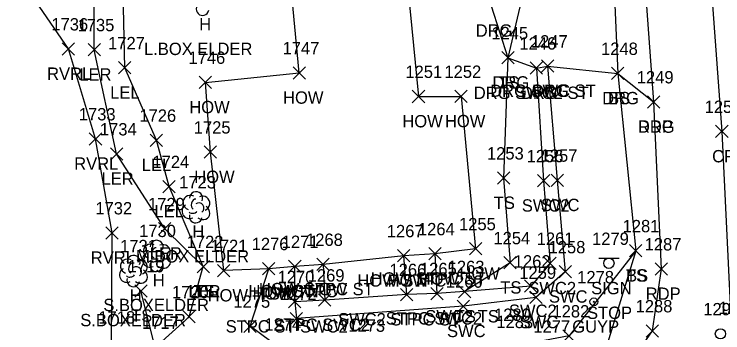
# Model space of a CAD drawing. Extents: x 1461855 to 1464118, y 556196 to 557441.
# Drawn here: x 1462302.6 to 1462417.3, y 556452.7 to 556504.3 of the extents above; entities that cross this region are included whole.
import ezdxf

# ---------------------------------------------------------------- set-up
doc = ezdxf.new("R2010")
doc.units = 0
for name, color, linetype in [('L_A', 7, 'Continuous'), ('L_C', 7, 'Continuous'), ('L_I', 7, 'Continuous'), ('L_TIC', 7, 'Continuous'), ('LARO', 7, 'Continuous'), ('LAWE', 7, 'Continuous'), ('LBC', 7, 'Continuous'), ('LBF', 7, 'Continuous'), ('LELB', 7, 'Continuous'), ('LTD', 7, 'Continuous'), ('P_A', 7, 'Continuous'), ('P_I', 7, 'Continuous'), ('P_TIC', 7, 'Continuous'), ('PET', 7, 'Continuous'), ('PRC', 7, 'Continuous'), ('R_A', 7, 'Continuous'), ('R_I', 7, 'Continuous'), ('R_TIC', 7, 'Continuous'), ('RDG', 7, 'Continuous'), ('RSW', 7, 'Continuous'), ('S_A', 7, 'Continuous'), ('S_C', 7, 'Continuous'), ('S_I', 7, 'Continuous'), ('SSGN', 7, 'Continuous'), ('U_A', 7, 'Continuous'), ('U_I', 7, 'Continuous'), ('UPGW', 7, 'Continuous'), ('UUMH', 7, 'Continuous')]:
    doc.layers.add(name, color=color, linetype=linetype)

msp = doc.modelspace()

# ---------------------------------------------------------------- linework, layer by layer
at = {"layer": 'L_TIC'}
for points in [[(1462310.37, 556497.7), (1462312.37, 556499.7)], [(1462312.37, 556497.7), (1462310.37, 556499.7)], [(1462314.55, 556497.58), (1462316.55, 556499.58)], [(1462316.55, 556497.58), (1462314.55, 556499.58)], [(1462381.5, 556496.28), (1462383.5, 556498.28)], [(1462383.5, 556496.28), (1462381.5, 556498.28)], [(1462319.5, 556494.65), (1462321.5, 556496.65)], [(1462321.5, 556494.65), (1462319.5, 556496.65)], [(1462347.73, 556493.83), (1462349.73, 556495.83)], [(1462349.73, 556493.83), (1462347.73, 556495.83)], [(1462399.26, 556493.74), (1462401.26, 556495.74)], [(1462401.26, 556493.74), (1462399.26, 556495.74)], [(1462332.55, 556492.29), (1462334.55, 556494.29)], [(1462334.55, 556492.29), (1462332.55, 556494.29)], [(1462367.02, 556490), (1462369.02, 556492)], [(1462369.02, 556490), (1462367.02, 556492)], [(1462373.91, 556490.02), (1462375.91, 556492.02)], [(1462375.91, 556490.02), (1462373.91, 556492.02)], [(1462314.76, 556483.13), (1462316.76, 556485.13)], [(1462316.76, 556483.13), (1462314.76, 556485.13)], [(1462324.61, 556482.91), (1462326.61, 556484.91)], [(1462326.61, 556482.91), (1462324.61, 556484.91)], [(1462318.16, 556480.69), (1462320.16, 556482.69)], [(1462320.16, 556480.69), (1462318.16, 556482.69)], [(1462333.35, 556480.99), (1462335.35, 556482.99)], [(1462335.35, 556480.99), (1462333.35, 556482.99)], [(1462380.8, 556476.79), (1462382.8, 556478.79)], [(1462382.8, 556476.79), (1462380.8, 556478.79)], [(1462326.67, 556475.4), (1462328.67, 556477.4)], [(1462328.67, 556475.4), (1462326.67, 556477.4)], [(1462317.43, 556467.89), (1462319.43, 556469.89)], [(1462319.43, 556467.89), (1462317.43, 556469.89)], [(1462325.96, 556468.57), (1462327.96, 556470.57)], [(1462327.96, 556468.57), (1462325.96, 556470.57)], [(1462369.67, 556464.51), (1462371.67, 556466.51)], [(1462371.67, 556464.51), (1462369.67, 556466.51)], [(1462369.67, 556464.51), (1462371.67, 556466.51)], [(1462371.67, 556464.51), (1462369.67, 556466.51)], [(1462376.27, 556465.33), (1462378.27, 556467.33)], [(1462378.27, 556465.33), (1462376.27, 556467.33)], [(1462402.17, 556465), (1462404.17, 556467)], [(1462404.17, 556465), (1462402.17, 556467)], [(1462402.17, 556465), (1462404.17, 556467)], [(1462404.17, 556465), (1462402.17, 556467)], [(1462364.63, 556464.19), (1462366.63, 556466.19)], [(1462366.63, 556464.19), (1462364.63, 556466.19)], [(1462364.63, 556464.19), (1462366.63, 556466.19)], [(1462366.63, 556464.19), (1462364.63, 556466.19)], [(1462332.2, 556462.44), (1462334.2, 556464.44)], [(1462334.2, 556462.44), (1462332.2, 556464.44)], [(1462332.2, 556462.44), (1462334.2, 556464.44)], [(1462334.2, 556462.44), (1462332.2, 556464.44)], [(1462332.2, 556462.44), (1462334.2, 556464.44)], [(1462334.2, 556462.44), (1462332.2, 556464.44)], [(1462342.78, 556462.1), (1462344.78, 556464.1)], [(1462344.78, 556462.1), (1462342.78, 556464.1)], [(1462342.78, 556462.1), (1462344.78, 556464.1)], [(1462344.78, 556462.1), (1462342.78, 556464.1)], [(1462347.01, 556462.46), (1462349.01, 556464.46)], [(1462349.01, 556462.46), (1462347.01, 556464.46)], [(1462347.01, 556462.46), (1462349.01, 556464.46)], [(1462349.01, 556462.46), (1462347.01, 556464.46)], [(1462351.57, 556462.79), (1462353.57, 556464.79)], [(1462353.57, 556462.79), (1462351.57, 556464.79)], [(1462351.57, 556462.79), (1462353.57, 556464.79)], [(1462353.57, 556462.79), (1462351.57, 556464.79)], [(1462381.84, 556463.06), (1462383.84, 556465.06)], [(1462383.84, 556463.06), (1462381.84, 556465.06)], [(1462335.52, 556461.79), (1462337.52, 556463.79)], [(1462337.52, 556461.79), (1462335.52, 556463.79)], [(1462322.11, 556458.5), (1462324.11, 556460.5)], [(1462324.11, 556458.5), (1462322.11, 556460.5)], [(1462365.12, 556457.9), (1462367.12, 556459.9)], [(1462367.12, 556457.9), (1462365.12, 556459.9)], [(1462370, 556458.05), (1462372, 556460.05)], [(1462372, 556458.05), (1462370, 556460.05)], [(1462374.48, 556458.39), (1462376.48, 556460.39)], [(1462376.48, 556458.39), (1462374.48, 556460.39)], [(1462347, 556456.75), (1462349, 556458.75)], [(1462349, 556456.75), (1462347, 556458.75)], [(1462351.85, 556457.01), (1462353.85, 556459.01)], [(1462353.85, 556457.01), (1462351.85, 556459.01)], [(1462329.91, 556454.31), (1462331.91, 556456.31)], [(1462331.91, 556454.31), (1462329.91, 556456.31)], [(1462339.76, 556452.77), (1462341.76, 556454.77)], [(1462341.76, 556452.77), (1462339.76, 556454.77)], [(1462391.39, 556451.19), (1462393.39, 556453.19)], [(1462393.39, 556451.19), (1462391.39, 556453.19)]]:
    msp.add_lwpolyline(points, dxfattribs=at)
at = {"layer": 'LARO'}
for points in [[(1462333.2, 556463.44), (1462326.96, 556469.57), (1462319.16, 556481.69), (1462315.55, 556498.58), (1462315.61, 556513.99), (1462326.32, 556521.07)], [(1462333.2, 556463.44), (1462327.67, 556476.4), (1462325.61, 556483.91), (1462320.5, 556495.65), (1462320.11, 556512.8), (1462326.32, 556521.07)]]:
    msp.add_lwpolyline(points, dxfattribs=at)
at = {"layer": 'LAWE'}
msp.add_lwpolyline([(1462349.42, 556312.26), (1462347.88, 556323.02), (1462343.78, 556341.46), (1462337.18, 556366.3), (1462336.39, 556385.54), (1462332.39, 556400.16), (1462328.25, 556406.01), (1462322.28, 556416.09), (1462319.22, 556425.25), (1462318.05, 556436.55), (1462318.36, 556451.21), (1462318.43, 556468.89), (1462315.76, 556484.13), (1462311.37, 556498.7), (1462302.6, 556511.6)], dxfattribs=at)
at = {"layer": 'LBC'}
msp.add_lwpolyline([(1462365.55, 556516.39), (1462368.02, 556491), (1462374.91, 556491.02), (1462377.27, 556466.33), (1462370.67, 556465.51), (1462365.63, 556465.19), (1462352.57, 556463.79), (1462348.01, 556463.46), (1462343.78, 556463.1), (1462336.52, 556462.79), (1462334.35, 556481.99), (1462333.55, 556493.29), (1462348.73, 556494.83), (1462346.86, 556514.38), (1462349.85, 556514.8), (1462349.13, 556520.74), (1462355.11, 556521.53), (1462355.47, 556515.9)], dxfattribs=at)
at = {"layer": 'LBF'}
for points in [[(1462370.67, 556465.51), (1462371, 556459.05)], [(1462366.12, 556458.9), (1462365.63, 556465.19)], [(1462348, 556457.75), (1462348.01, 556463.46)], [(1462352.57, 556463.79), (1462352.85, 556458.01)]]:
    msp.add_lwpolyline(points, dxfattribs=at)
at = {"layer": 'LELB'}
for points in [[(1462392.6, 556582.28), (1462394.16, 556573.28), (1462392.25, 556560.75), (1462384.18, 556539.63), (1462388.23, 556521.88), (1462382.5, 556497.28), (1462381.8, 556477.79), (1462382.84, 556464.06), (1462375.48, 556459.39)], [(1462397.76, 556560.35), (1462398.93, 556525.64), (1462400.26, 556494.74), (1462403.17, 556466), (1462397.35, 556446.97), (1462388.69, 556445.8), (1462367.43, 556444.36), (1462357.72, 556443.74), (1462341.15, 556446.51)], [(1462403.17, 556466), (1462392.39, 556452.19), (1462383.31, 556450.47), (1462367.43, 556444.36)], [(1462328.51, 556438.01), (1462325.41, 556450.35), (1462330.91, 556455.31), (1462333.2, 556463.44)], [(1462359.35, 556449.87), (1462345.78, 556450.06), (1462340.76, 556453.77), (1462343.78, 556463.1)], [(1462327.98, 556421.29), (1462322.63, 556425.06), (1462324.05, 556436.25), (1462325.41, 556450.35), (1462323.11, 556459.5)]]:
    msp.add_lwpolyline(points, dxfattribs=at)
at = {"layer": 'LTD'}
for p, q in [((1462331.99, 556473.1), (1462331.99, 556473.1)), ((1462331.99, 556473.1), (1462331.99, 556473.1)), ((1462325.6, 556465.22), (1462325.6, 556465.22)), ((1462325.6, 556465.22), (1462325.6, 556465.22)), ((1462321.88, 556462.77), (1462321.88, 556462.77)), ((1462321.88, 556462.77), (1462321.88, 556462.77))]:
    msp.add_line(p, q, dxfattribs=at)
for centre in [(1462332.04, 556474.53), (1462325.65, 556466.65), (1462321.92, 556464.2)]:
    msp.add_arc(centre, 1.05, 335.5272, 180.9563, dxfattribs=at)
for centre, major_axis, ratio, start_param, end_param in [((1462333.09, 556505.22), (0.26, 1.06), 0.942809, 1.570796, 4.712389), ((1462331.2, 556473.77), (1.21, -0.51), 0.895232, 1.570796, 4.712389), ((1462331.78, 556473.56), (-0.208, -0.792), 0.645439, 3.141593, 6.283185), ((1462333.03, 556473.68), (-1.14, -0.48), 0.949671, 1.570796, 4.712389), ((1462330.91, 556472.39), (0.58, -1.04), 0.959034, 3.141593, 6.283185), ((1462332.49, 556472.93), (-0.5, 0.667), 0.989748, 3.141593, 6.283185), ((1462331.53, 556472.35), (-0.625, -0.083), 0.423636, 0, 3.141593), ((1462332.99, 556472.27), (-1.09, 0.79), 0.841452, 1.570796, 4.712389), ((1462331.99, 556471.6), (0.26, 1.06), 0.942809, 1.570796, 4.712389), ((1462324.81, 556465.88), (1.21, -0.51), 0.895232, 1.570796, 4.712389), ((1462325.39, 556465.68), (-0.208, -0.792), 0.645439, 3.141593, 6.283185), ((1462326.64, 556465.8), (-1.14, -0.48), 0.949671, 1.570796, 4.712389), ((1462324.52, 556464.51), (0.58, -1.04), 0.959034, 3.141593, 6.283185), ((1462326.1, 556465.05), (-0.5, 0.667), 0.989748, 3.141593, 6.283185), ((1462326.6, 556464.38), (-1.09, 0.79), 0.841452, 1.570796, 4.712389), ((1462321.08, 556463.44), (1.21, -0.51), 0.895232, 1.570796, 4.712389), ((1462321.67, 556463.23), (-0.208, -0.792), 0.645439, 3.141593, 6.283185), ((1462322.92, 556463.35), (-1.14, -0.48), 0.949671, 1.570796, 4.712389), ((1462325.14, 556464.47), (-0.625, -0.083), 0.423636, 0, 3.141593), ((1462320.79, 556462.06), (0.58, -1.04), 0.959034, 3.141593, 6.283185), ((1462322.38, 556462.6), (-0.5, 0.667), 0.989748, 3.141593, 6.283185), ((1462325.6, 556463.72), (0.26, 1.06), 0.942809, 1.570796, 4.712389), ((1462321.42, 556462.02), (-0.625, -0.083), 0.423636, 0, 3.141593), ((1462322.88, 556461.94), (-1.09, 0.79), 0.841452, 1.570796, 4.712389), ((1462321.88, 556461.27), (0.26, 1.06), 0.942809, 1.570796, 4.712389)]:
    msp.add_ellipse(centre, major_axis=major_axis, ratio=ratio, start_param=start_param, end_param=end_param, dxfattribs=at)
at = {"layer": 'P_TIC'}
for points in [[(1462405.05, 556489.12), (1462407.05, 556491.12)], [(1462407.05, 556489.12), (1462405.05, 556491.12)], [(1462416.1, 556484.33), (1462418.1, 556486.33)], [(1462418.1, 556484.33), (1462416.1, 556486.33)], [(1462406.3, 556462.05), (1462408.3, 556464.05)], [(1462408.3, 556462.05), (1462406.3, 556464.05)], [(1462404.84, 556452.02), (1462406.84, 556454.02)], [(1462406.84, 556452.02), (1462404.84, 556454.02)]]:
    msp.add_lwpolyline(points, dxfattribs=at)
at = {"layer": 'PET'}
msp.add_lwpolyline([(1462398.06, 556593.15), (1462400.02, 556575.06), (1462401.08, 556560.86), (1462403.29, 556527.85), (1462406.05, 556490.12), (1462407.3, 556463.05), (1462405.84, 556453.02), (1462399.79, 556444.3), (1462382.48, 556434.45)], dxfattribs=at)
at = {"layer": 'PRC'}
msp.add_lwpolyline([(1462408.92, 556592.16), (1462412.2, 556557.56), (1462413.99, 556527.84), (1462417.1, 556485.33), (1462418.69, 556452.73), (1462415.65, 556430.87), (1462414.08, 556417.65)], dxfattribs=at)
at = {"layer": 'R_TIC'}
for points in [[(1462381.5, 556496.28), (1462383.5, 556498.28)], [(1462383.5, 556496.28), (1462381.5, 556498.28)], [(1462386.1, 556494.6), (1462388.1, 556496.6)], [(1462388.1, 556494.6), (1462386.1, 556496.6)], [(1462386.1, 556494.6), (1462388.1, 556496.6)], [(1462388.1, 556494.6), (1462386.1, 556496.6)], [(1462387.91, 556494.94), (1462389.91, 556496.94)], [(1462389.91, 556494.94), (1462387.91, 556496.94)], [(1462387.91, 556494.94), (1462389.91, 556496.94)], [(1462389.91, 556494.94), (1462387.91, 556496.94)], [(1462399.26, 556493.74), (1462401.26, 556495.74)], [(1462401.26, 556493.74), (1462399.26, 556495.74)], [(1462405.05, 556489.12), (1462407.05, 556491.12)], [(1462407.05, 556489.12), (1462405.05, 556491.12)], [(1462387.27, 556476.34), (1462389.27, 556478.34)], [(1462389.27, 556476.34), (1462387.27, 556478.34)], [(1462389.47, 556476.43), (1462391.47, 556478.43)], [(1462391.47, 556476.43), (1462389.47, 556478.43)], [(1462388.32, 556462.96), (1462390.32, 556464.96)], [(1462390.32, 556462.96), (1462388.32, 556464.96)], [(1462390.77, 556461.59), (1462392.77, 556463.59)], [(1462392.77, 556461.59), (1462390.77, 556463.59)], [(1462385.18, 556459.28), (1462387.18, 556461.28)], [(1462387.18, 556459.28), (1462385.18, 556461.28)], [(1462365.12, 556457.9), (1462367.12, 556459.9)], [(1462367.12, 556457.9), (1462365.12, 556459.9)], [(1462370, 556458.05), (1462372, 556460.05)], [(1462372, 556458.05), (1462370, 556460.05)], [(1462374.48, 556458.39), (1462376.48, 556460.39)], [(1462376.48, 556458.39), (1462374.48, 556460.39)], [(1462347, 556456.75), (1462349, 556458.75)], [(1462349, 556456.75), (1462347, 556458.75)], [(1462351.85, 556457.01), (1462353.85, 556459.01)], [(1462353.85, 556457.01), (1462351.85, 556459.01)], [(1462386.03, 556457.45), (1462388.03, 556459.45)], [(1462388.03, 556457.45), (1462386.03, 556459.45)], [(1462374.28, 556456.01), (1462376.28, 556458.01)], [(1462376.28, 556456.01), (1462374.28, 556458.01)], [(1462347.27, 556454.01), (1462349.27, 556456.01)], [(1462349.27, 556454.01), (1462347.27, 556456.01)], [(1462347.27, 556454.01), (1462349.27, 556456.01)], [(1462349.27, 556454.01), (1462347.27, 556456.01)]]:
    msp.add_lwpolyline(points, dxfattribs=at)
at = {"layer": 'RDG'}
msp.add_lwpolyline([(1462339.36, 556595.74), (1462349.96, 556573.72), (1462350.64, 556554.62), (1462363.11, 556531.92), (1462365.3, 556525.05), (1462369.29, 556516.9), (1462379.79, 556505.69), (1462382.5, 556497.28), (1462387.1, 556495.6), (1462388.91, 556495.94), (1462400.26, 556494.74), (1462406.05, 556490.12)], dxfattribs=at)
at = {"layer": 'RSW'}
for points in [[(1462387.1, 556495.6), (1462388.27, 556477.34), (1462389.32, 556463.96), (1462386.18, 556460.28), (1462375.48, 556459.39), (1462371, 556459.05), (1462366.12, 556458.9), (1462352.85, 556458.01), (1462348, 556457.75), (1462348.27, 556455.01)], [(1462388.91, 556495.94), (1462390.47, 556477.43), (1462391.77, 556462.59), (1462387.03, 556458.45), (1462375.28, 556457.01), (1462348.27, 556455.01)]]:
    msp.add_lwpolyline(points, dxfattribs=at)
at = {"layer": 'SSGN'}
for p, q in [((1462397.18, 556464.8), (1462400.51, 556464.8)), ((1462398.83, 556463.97), (1462398.83, 556463.97))]:
    msp.add_line(p, q, dxfattribs=at)
msp.add_circle((1462398.83, 556463.97), 0.833, dxfattribs=at)
at = {"layer": 'UPGW'}
for radius in [0.625, 0.0833]:
    msp.add_circle((1462396.39, 556457.73), radius, dxfattribs=at)
at = {"layer": 'UUMH'}
msp.add_circle((1462416.88, 556452.54), 0.833, dxfattribs=at)

# ---------------------------------------------------------------- texts
at = {"layer": 'L_A'}
for s, p in [('H', (1462332.53, 556501.72)), ('RVRL', (1462307.93, 556493.7)), ('LER', (1462313.14, 556493.58)), ('TS', (1462380.91, 556492.28)), ('LEL', (1462318.13, 556490.65)), ('HOW', (1462346.11, 556489.83)), ('BS', (1462398.7, 556489.74)), ('HOW', (1462330.94, 556488.29)), ('HOW', (1462365.41, 556486)), ('HOW', (1462372.3, 556486.02)), ('RVRL', (1462312.32, 556479.13)), ('LEL', (1462323.25, 556478.91)), ('HOW', (1462331.74, 556476.99)), ('LER', (1462316.74, 556476.69)), ('TS', (1462380.2, 556472.79)), ('LEL', (1462325.3, 556471.4)), ('H', (1462331.42, 556468.1)), ('LER', (1462324.54, 556464.57)), ('RVRL', (1462315, 556463.89)), ('HOW', (1462374.65, 556461.33)), ('TS', (1462401.58, 556461)), ('BS', (1462401.61, 556461)), ('H', (1462325.03, 556460.22)), ('HOW STPC', (1462358.13, 556460.19)), ('HOW STPC ST', (1462360.3, 556460.51)), ('HOW', (1462363.02, 556460.19)), ('HOW', (1462368.06, 556460.51)), ('HOW STPC ST', (1462342.2, 556458.79)), ('HOW', (1462349.95, 556458.79)), ('TS', (1462381.25, 556459.06)), ('H', (1462321.31, 556457.77)), ('LER', (1462330.79, 556458.44)), ('LEL', (1462330.84, 556458.44)), ('TS', (1462331.61, 556458.44)), ('HOW', (1462333.9, 556457.79)), ('HOW STPC', (1462340.51, 556458.46)), ('HOW', (1462341.16, 556458.1)), ('TS', (1462342.19, 556458.1)), ('HOW', (1462345.4, 556458.46)), ('TS', (1462321.52, 556454.5)), ('STPC SWC2', (1462362.72, 556454.05)), ('TS', (1462373.89, 556454.39)), ('STPC SWC2', (1462344.57, 556453.01)), ('SWC2 STPC ST', (1462355.01, 556453.9)), ('STPC ST SWC2', (1462336.82, 556452.75))]:
    msp.add_text(s, height=2, dxfattribs=at).set_placement(p)
at = {"layer": 'L_C'}
for s, p in [('L.BOX ELDER', (1462323.61, 556497.72)), ('M.BOX ELDER', (1462322.33, 556464.1)), ('S.BOXELDER', (1462317.03, 556456.22)), ('S.BOXELDER', (1462313.3, 556453.77))]:
    msp.add_text(s, height=2, dxfattribs=at).set_placement(p)
at = {"layer": 'L_I'}
for s, p in [('1736', (1462308.62, 556501.7)), ('1735', (1462312.86, 556501.58)), ('1245', (1462379.81, 556500.28)), ('1727', (1462317.8, 556498.65)), ('1747', (1462346.03, 556497.83)), ('1248', (1462397.56, 556497.74)), ('1746', (1462330.8, 556496.29)), ('1251', (1462365.9, 556494)), ('1252', (1462372.22, 556494.02)), ('1733', (1462313.06, 556487.13)), ('1726', (1462322.86, 556486.91)), ('1725', (1462331.66, 556484.99)), ('1734', (1462316.47, 556484.69)), ('1253', (1462379.1, 556480.79)), ('1724', (1462324.97, 556479.4)), ('1723', (1462329.3, 556476.1)), ('1729', (1462324.26, 556472.57)), ('1732', (1462315.74, 556471.89)), ('1255', (1462374.58, 556469.33)), ('1281', (1462401.05, 556469)), ('1281', (1462401.05, 556469)), ('1730', (1462322.82, 556468.22)), ('1267', (1462362.89, 556468.19)), ('1267', (1462362.89, 556468.19)), ('1264', (1462367.93, 556468.51)), ('1264', (1462367.93, 556468.51)), ('1268', (1462349.83, 556466.79)), ('1268', (1462349.83, 556466.79)), ('1254', (1462380.15, 556467.06)), ('1731', (1462319.75, 556465.77)), ('1722', (1462330.51, 556466.44)), ('1722', (1462330.51, 556466.44)), ('1722', (1462330.51, 556466.44)), ('1721', (1462334.39, 556465.79)), ('1276', (1462341.03, 556466.1)), ('1276', (1462341.03, 556466.1)), ('1271', (1462345.89, 556466.46)), ('1271', (1462345.89, 556466.46)), ('1719', (1462320.97, 556462.5)), ('1265', (1462368.26, 556462.05)), ('1263', (1462372.74, 556462.39)), ('1269', (1462350.1, 556461.01)), ('1266', (1462363.33, 556461.9)), ('1270', (1462345.22, 556460.75)), ('1720', (1462328.13, 556458.31)), ('1275', (1462338.07, 556456.77)), ('1282', (1462389.7, 556455.19)), ('1718', (1462316.23, 556454.21)), ('1717', (1462323.29, 556453.35)), ('1717', (1462323.29, 556453.35)), ('1274', (1462343.09, 556453.06)), ('1274', (1462343.09, 556453.06)), ('1273', (1462356.66, 556452.87)), ('1273', (1462356.66, 556452.87)), ('1283', (1462380.62, 556453.47)), ('1277', (1462386.6, 556452.71))]:
    msp.add_text(s, height=2, dxfattribs=at).set_placement(p)
at = {"layer": 'P_A'}
for s, p in [('RDP', (1462403.53, 556485.12)), ('CR', (1462415.53, 556480.33)), ('RDP', (1462404.79, 556458.05))]:
    msp.add_text(s, height=2, dxfattribs=at).set_placement(p)
at = {"layer": 'P_I'}
for s, p in [('1249', (1462403.34, 556493.12)), ('1250', (1462414.32, 556488.33)), ('1287', (1462404.61, 556466.05)), ('1288', (1462403.15, 556456.02)), ('1291', (1462416.57, 556455.73))]:
    msp.add_text(s, height=2, dxfattribs=at).set_placement(p)
at = {"layer": 'R_A'}
for s, p in [('DRG', (1462377.28, 556500.69)), ('DRG', (1462379.99, 556492.28)), ('DRG SWC ST', (1462379.62, 556490.94)), ('DRG', (1462386.39, 556490.94)), ('DRG SWC2 ST', (1462376.97, 556490.6)), ('DRG', (1462384.59, 556490.6)), ('DRG', (1462397.74, 556489.74)), ('DRG', (1462403.53, 556485.12)), ('SWC', (1462387.83, 556472.43)), ('SWC2', (1462384.74, 556472.34)), ('SWC2', (1462385.79, 556458.96)), ('SWC', (1462389.13, 556457.59)), ('SWC2', (1462382.65, 556455.28)), ('STPC SWC2', (1462362.72, 556454.05)), ('SWC2 TS', (1462369.13, 556454.39)), ('STPC SWC2', (1462344.57, 556453.01)), ('SWC2 STPC ST', (1462355.01, 556453.9)), ('SWC', (1462384.39, 556453.45)), ('STPC ST SWC2', (1462336.82, 556452.75)), ('SWC', (1462372.64, 556452.01))]:
    msp.add_text(s, height=2, dxfattribs=at).set_placement(p)
at = {"layer": 'R_I'}
for s, p in [('1245', (1462379.81, 556500.28)), ('1247', (1462386.21, 556498.94)), ('1247', (1462386.21, 556498.94)), ('1246', (1462384.35, 556498.6)), ('1246', (1462384.35, 556498.6)), ('1248', (1462397.56, 556497.74)), ('1249', (1462403.34, 556493.12)), ('1257', (1462387.78, 556480.43)), ('1256', (1462385.52, 556480.34)), ('1261', (1462387.15, 556466.96)), ('1258', (1462389.07, 556465.59)), ('1262', (1462383.44, 556463.28)), ('1265', (1462368.26, 556462.05)), ('1263', (1462372.74, 556462.39)), ('1269', (1462350.1, 556461.01)), ('1266', (1462363.33, 556461.9)), ('1259', (1462384.33, 556461.45)), ('1270', (1462345.22, 556460.75)), ('1260', (1462372.45, 556460.01)), ('1272', (1462345.58, 556458.01)), ('1272', (1462345.58, 556458.01))]:
    msp.add_text(s, height=2, dxfattribs=at).set_placement(p)
at = {"layer": 'S_A'}
msp.add_text('SIGN', height=2, dxfattribs=at).set_placement((1462395.96, 556458.95))
at = {"layer": 'S_C'}
msp.add_text('STOP', height=2, dxfattribs=at).set_placement((1462395.29, 556454.95))
at = {"layer": 'S_I'}
msp.add_text('1279', height=2, dxfattribs=at).set_placement((1462396.11, 556466.95))
at = {"layer": 'U_A'}
msp.add_text('GUYP', height=2, dxfattribs=at).set_placement((1462392.9, 556452.73))
at = {"layer": 'U_I'}
for s, p in [('1278', (1462393.7, 556460.73)), ('1290', (1462414.1, 556455.54)), ('1280', (1462380.24, 556454.64))]:
    msp.add_text(s, height=2, dxfattribs=at).set_placement(p)

doc.saveas('drawing.dxf')
